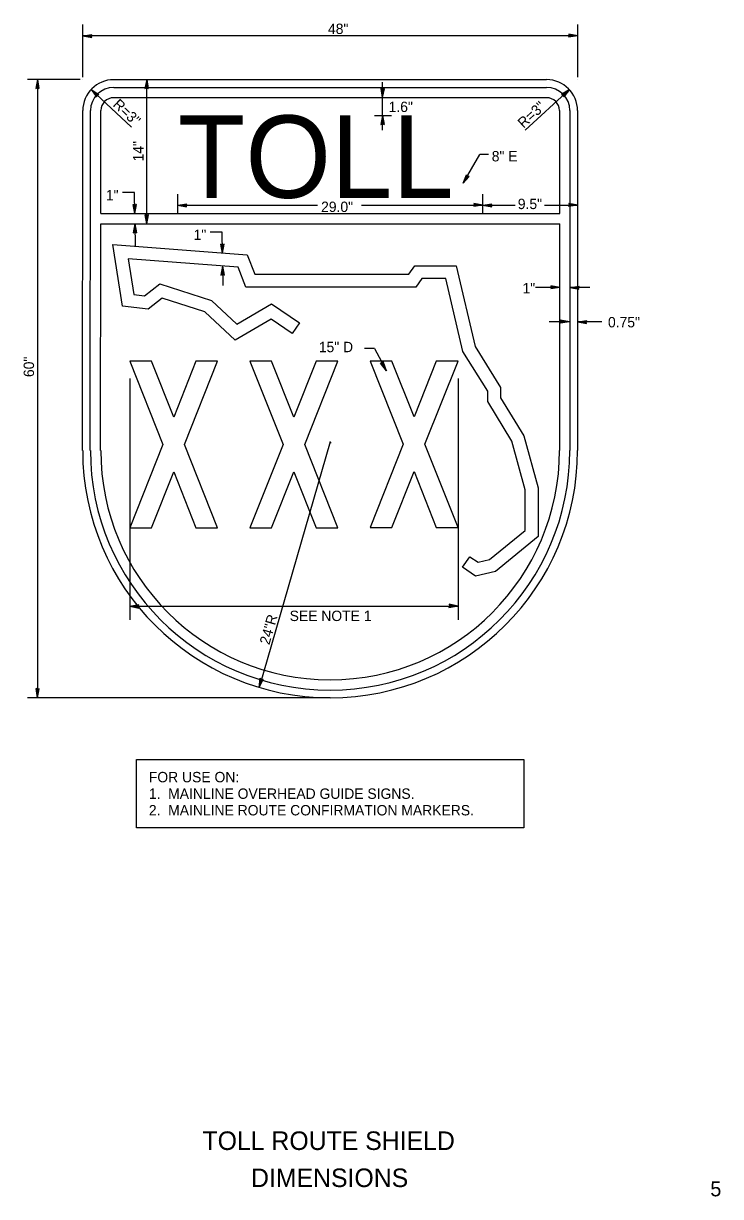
# Model space of a CAD drawing. Extents: x 52194 to 54069, y 8993 to 10153.
# Drawn here: x 53506 to 54069, y 9023 to 9972 of the extents above; entities that cross this region are included whole.
import ezdxf

# ---------------------------------------------------------------- set-up
doc = ezdxf.new("R2010")
doc.units = 0
for name, color, linetype in [('GSDims', 7, 'Continuous'), ('SignPanel', 7, 'Continuous'), ('TextLabel', 7, 'Continuous'), ('TextMisc', 7, 'Continuous'), ('TextShtNo', 7, 'Continuous')]:
    doc.layers.add(name, color=color, linetype=linetype)

msp = doc.modelspace()

# ---------------------------------------------------------------- linework, layer by layer
at = {"layer": 'GSDims'}
for p, q in [((53553.67, 9929.08), (53553.67, 9971.68)), ((53953.67, 9929.08), (53953.67, 9971.68)), ((53553.67, 9962.43), (53560.97, 9963.58)), ((53553.67, 9962.43), (53560.67, 9962.93)), ((53553.67, 9962.43), (53560.92, 9961.03)), ((53553.67, 9962.43), (53560.67, 9961.68)), ((53953.67, 9962.43), (53553.67, 9962.43)), ((53560.42, 9962.33), (53560.97, 9963.58)), ((53560.92, 9961.03), (53560.42, 9962.33)), ((53946.92, 9962.53), (53946.37, 9961.28)), ((53953.67, 9962.43), (53946.37, 9961.28)), ((53953.67, 9962.43), (53946.42, 9963.83)), ((53946.42, 9963.83), (53946.92, 9962.53)), ((53953.67, 9962.43), (53946.67, 9963.18)), ((53953.67, 9962.43), (53946.67, 9961.93)), ((53551.62, 9927.03), (53509.02, 9927.03)), ((53517.12, 9927.03), (53515.72, 9919.78)), ((53517.12, 9927.03), (53516.37, 9920.03)), ((53517.12, 9927.03), (53518.27, 9919.73)), ((53517.12, 9927.03), (53517.62, 9920.03)), ((53517.12, 9927.03), (53517.12, 9427.03)), ((53553.67, 9927.03), (53553.67, 9927.03)), ((53605.32, 9927.03), (53603.92, 9919.78)), ((53605.32, 9927.03), (53604.57, 9920.03)), ((53605.32, 9927.03), (53606.47, 9919.73)), ((53605.32, 9927.03), (53605.82, 9920.03)), ((53605.32, 9810.33), (53605.32, 9927.03)), ((53953.67, 9927.03), (53953.67, 9927.03)), ((53515.72, 9919.78), (53517.02, 9920.28)), ((53517.02, 9920.28), (53518.27, 9919.73)), ((53560.47, 9919.13), (53566.57, 9914.98)), ((53560.47, 9919.13), (53564.77, 9913.13)), ((53560.47, 9919.13), (53565.07, 9913.83)), ((53560.47, 9919.13), (53565.92, 9914.68)), ((53560.47, 9919.13), (53592.92, 9888.53)), ((53603.92, 9919.78), (53605.22, 9920.28)), ((53605.22, 9920.28), (53606.47, 9919.73)), ((53796.02, 9912.43), (53794.87, 9919.73)), ((53796.12, 9919.18), (53794.87, 9919.73)), ((53796.02, 9912.43), (53795.52, 9919.43)), ((53796.02, 9912.43), (53796.02, 9925.03)), ((53796.02, 9912.43), (53797.42, 9919.68)), ((53796.02, 9912.43), (53796.77, 9919.43)), ((53797.42, 9919.68), (53796.12, 9919.18)), ((53946.97, 9918.93), (53911.22, 9886.03)), ((53946.97, 9918.93), (53940.67, 9915.03)), ((53946.97, 9918.93), (53941.32, 9914.73)), ((53946.97, 9918.93), (53942.17, 9913.83)), ((53946.97, 9918.93), (53942.37, 9913.13)), ((53564.77, 9913.13), (53565.27, 9914.43)), ((53565.27, 9914.43), (53566.57, 9914.98)), ((53796.02, 9898.03), (53796.02, 9912.43)), ((53940.67, 9915.03), (53941.92, 9914.43)), ((53941.92, 9914.43), (53942.37, 9913.13)), ((53789.42, 9898.03), (53803.07, 9898.03)), ((53796.02, 9898.03), (53794.62, 9890.78)), ((53796.02, 9898.03), (53795.27, 9891.03)), ((53796.02, 9886.03), (53796.02, 9898.03)), ((53796.02, 9898.03), (53797.17, 9890.73)), ((53796.02, 9898.03), (53796.52, 9891.03)), ((53794.62, 9890.78), (53795.92, 9891.28)), ((53795.92, 9891.28), (53797.17, 9890.73)), ((53861.07, 9843.13), (53874.47, 9866.33)), ((53881.67, 9866.33), (53874.47, 9866.33)), ((53861.07, 9843.13), (53863.72, 9850.03)), ((53861.07, 9843.13), (53864.17, 9849.43)), ((53861.07, 9843.13), (53865.22, 9848.83)), ((53861.07, 9843.13), (53865.92, 9848.73)), ((53864.52, 9848.88), (53863.72, 9850.03)), ((53865.92, 9848.73), (53864.52, 9848.88)), ((53595.47, 9835.68), (53585.72, 9835.68)), ((53595.62, 9818.73), (53595.47, 9835.68)), ((53630.37, 9818.63), (53630.37, 9834.23)), ((53877.07, 9818.63), (53877.07, 9834.23)), ((53595.62, 9818.73), (53594.37, 9826.03)), ((53595.67, 9825.48), (53594.37, 9826.03)), ((53595.62, 9818.73), (53595.07, 9825.73)), ((53595.62, 9818.73), (53596.97, 9826.03)), ((53595.62, 9818.73), (53596.27, 9825.73)), ((53596.97, 9826.03), (53595.67, 9825.48)), ((53630.37, 9825.43), (53637.67, 9826.58)), ((53630.37, 9825.43), (53637.37, 9825.93)), ((53630.37, 9825.43), (53637.62, 9824.03)), ((53630.37, 9825.43), (53637.37, 9824.68)), ((53630.37, 9825.43), (53743.27, 9825.43)), ((53637.12, 9825.33), (53637.67, 9826.58)), ((53637.62, 9824.03), (53637.12, 9825.33)), ((53778.85, 9825.43), (53877.07, 9825.43)), ((53870.32, 9825.53), (53869.77, 9824.28)), ((53877.07, 9825.43), (53869.77, 9824.28)), ((53877.07, 9825.43), (53869.82, 9826.83)), ((53869.82, 9826.83), (53870.32, 9825.53)), ((53877.07, 9825.43), (53870.07, 9826.18)), ((53877.07, 9825.43), (53870.07, 9824.93)), ((53877.07, 9825.43), (53884.37, 9826.58)), ((53877.07, 9825.43), (53884.07, 9825.93)), ((53877.07, 9825.43), (53884.32, 9824.03)), ((53877.07, 9825.43), (53884.07, 9824.68)), ((53877.07, 9825.43), (53903.13, 9825.43)), ((53883.82, 9825.33), (53884.37, 9826.58)), ((53884.32, 9824.03), (53883.82, 9825.33)), ((53926.79, 9825.43), (53953.67, 9825.43)), ((53946.92, 9825.53), (53946.37, 9824.28)), ((53953.67, 9825.43), (53946.37, 9824.28)), ((53953.67, 9825.43), (53946.42, 9826.83)), ((53946.42, 9826.83), (53946.92, 9825.53)), ((53953.67, 9825.43), (53946.67, 9826.18)), ((53953.67, 9825.43), (53946.67, 9824.93)), ((53605.32, 9810.33), (53604.17, 9817.63)), ((53605.42, 9817.08), (53604.17, 9817.63)), ((53605.32, 9810.33), (53604.82, 9817.33)), ((53605.32, 9810.33), (53606.72, 9817.58)), ((53605.32, 9810.33), (53606.07, 9817.33)), ((53606.72, 9817.58), (53605.42, 9817.08)), ((53595.72, 9810.43), (53594.37, 9803.13)), ((53594.37, 9803.13), (53595.67, 9803.68)), ((53595.72, 9810.43), (53595.07, 9803.43)), ((53595.67, 9803.68), (53596.97, 9803.13)), ((53595.72, 9810.43), (53596.97, 9803.13)), ((53595.72, 9810.43), (53596.27, 9803.43)), ((53595.72, 9810.43), (53595.92, 9792.38)), ((53666.4, 9803.68), (53656.65, 9803.68)), ((53666.55, 9786.73), (53666.4, 9803.68)), ((53666.55, 9786.73), (53665.3, 9794.03)), ((53666.6, 9793.48), (53665.3, 9794.03)), ((53666.55, 9786.73), (53666, 9793.73)), ((53666.55, 9786.73), (53667.9, 9794.03)), ((53666.55, 9786.73), (53667.2, 9793.73)), ((53667.9, 9794.03), (53666.6, 9793.48)), ((53666.68, 9776.22), (53665.33, 9768.92)), ((53666.68, 9776.22), (53666.03, 9769.22)), ((53666.68, 9776.22), (53667.93, 9768.92)), ((53666.68, 9776.22), (53667.23, 9769.22)), ((53666.68, 9776.22), (53666.85, 9760.38)), ((53665.33, 9768.92), (53666.63, 9769.47)), ((53666.63, 9769.47), (53667.93, 9768.92)), ((53939.17, 9758.88), (53919.62, 9758.88)), ((53932.42, 9758.98), (53931.87, 9757.73)), ((53939.17, 9758.88), (53931.87, 9757.73)), ((53939.17, 9758.88), (53931.92, 9760.28)), ((53931.92, 9760.28), (53932.42, 9758.98)), ((53939.17, 9758.88), (53932.17, 9759.63)), ((53939.17, 9758.88), (53932.17, 9758.38)), ((53947.47, 9758.88), (53954.77, 9760.03)), ((53947.47, 9758.88), (53954.47, 9759.38)), ((53947.47, 9758.88), (53954.72, 9757.48)), ((53947.47, 9758.88), (53954.47, 9758.13)), ((53963.47, 9758.88), (53947.47, 9758.88)), ((53954.22, 9758.78), (53954.77, 9760.03)), ((53954.72, 9757.48), (53954.22, 9758.78)), ((53947.02, 9731.08), (53930.52, 9731.08)), ((53940.27, 9731.18), (53939.72, 9729.93)), ((53947.02, 9731.08), (53939.72, 9729.93)), ((53947.02, 9731.08), (53939.77, 9732.48)), ((53939.77, 9732.48), (53940.27, 9731.18)), ((53947.02, 9731.08), (53940.02, 9731.83)), ((53947.02, 9731.08), (53940.02, 9730.58)), ((53953.67, 9731.08), (53960.97, 9732.23)), ((53953.67, 9731.08), (53960.67, 9731.58)), ((53953.67, 9731.08), (53960.92, 9729.68)), ((53953.67, 9731.08), (53960.67, 9730.33)), ((53973.22, 9731.08), (53953.67, 9731.08)), ((53960.42, 9730.98), (53960.97, 9732.23)), ((53960.92, 9729.68), (53960.42, 9730.98)), ((53789.47, 9709.42), (53781.4, 9709.42)), ((53789.47, 9709.42), (53799.02, 9691.33)), ((53796.58, 9699), (53795.75, 9697.75)), ((53799.02, 9691.33), (53796.58, 9699)), ((53795.75, 9697.75), (53794.35, 9697.62)), ((53799.02, 9691.33), (53794.35, 9697.62)), ((53799.02, 9691.33), (53795.1, 9697.72)), ((53799.02, 9691.33), (53796.15, 9698.39)), ((53591.6, 9685.11), (53591.6, 9490.01)), ((53856.95, 9685.11), (53856.95, 9490.01)), ((53753.62, 9633.93), (53696.32, 9435.36)), ((53753.62, 9633.93), (53753.62, 9633.93)), ((53753.62, 9633.93), (53753.62, 9633.93)), ((53591.6, 9501.08), (53598.91, 9502.34)), ((53591.6, 9501.08), (53598.61, 9501.63)), ((53591.6, 9501.08), (53856.95, 9501.08)), ((53591.6, 9501.08), (53598.86, 9499.55)), ((53591.6, 9501.08), (53598.61, 9500.26)), ((53598.36, 9500.97), (53598.91, 9502.34)), ((53598.86, 9499.55), (53598.36, 9500.97)), ((53850.19, 9501.19), (53849.63, 9499.82)), ((53856.95, 9501.08), (53849.63, 9499.82)), ((53856.95, 9501.08), (53849.68, 9502.61)), ((53849.68, 9502.61), (53850.19, 9501.19)), ((53856.95, 9501.08), (53849.93, 9501.9)), ((53856.95, 9501.08), (53849.93, 9500.53)), ((53696.32, 9435.36), (53696.97, 9442.71)), ((53696.97, 9442.71), (53698.12, 9441.86)), ((53517.12, 9427.03), (53515.97, 9434.33)), ((53517.22, 9433.78), (53515.97, 9434.33)), ((53517.12, 9427.03), (53516.62, 9434.03)), ((53517.12, 9427.03), (53518.52, 9434.28)), ((53517.12, 9427.03), (53517.87, 9434.03)), ((53518.52, 9434.28), (53517.22, 9433.78)), ((53696.32, 9435.36), (53697.57, 9442.31)), ((53696.32, 9435.36), (53699.47, 9442.06)), ((53696.32, 9435.36), (53698.77, 9441.96)), ((53698.12, 9441.86), (53699.47, 9442.06)), ((53753.57, 9427.03), (53509.02, 9427.03)), ((53553.67, 9426.93), (53553.67, 9426.93))]:
    msp.add_line(p, q, dxfattribs=at)
for radius in [0.141, 0.141, 0.0707]:
    msp.add_circle((53753.62, 9633.93), radius, dxfattribs=at)
at = {"layer": 'SignPanel'}
for p, q in [((53578.67, 9927.03), (53928.57, 9927.03)), ((53578.67, 9920.73), (53928.57, 9920.73)), ((53578.67, 9912.43), (53928.57, 9912.43)), ((53553.57, 9626.93), (53553.67, 9902.03)), ((53559.77, 9626.93), (53559.87, 9902.03)), ((53568.17, 9818.63), (53568.17, 9902.03)), ((53939.17, 9818.63), (53939.17, 9902.03)), ((53947.47, 9626.93), (53947.47, 9902.03)), ((53953.67, 9626.93), (53953.67, 9902.03)), ((53568.17, 9818.63), (53620.37, 9818.63)), ((53620.37, 9818.63), (53939.17, 9818.63)), ((53568.07, 9626.93), (53568.17, 9810.33)), ((53568.17, 9810.33), (53939.17, 9810.33)), ((53939.17, 9626.93), (53939.17, 9810.33)), ((53577.98, 9793.57), (53686.64, 9785.19)), ((53585.72, 9743.87), (53577.98, 9793.57)), ((53686.64, 9785.19), (53692.71, 9769.56)), ((53679.26, 9775.24), (53590.37, 9782.1)), ((53590.37, 9782.1), (53594.86, 9753.3)), ((53685.54, 9759.08), (53679.26, 9775.24)), ((53817.33, 9769.56), (53822.03, 9776.5)), ((53822.03, 9776.5), (53855.56, 9776.5)), ((53855.56, 9776.5), (53870.74, 9711.18)), ((53692.71, 9769.56), (53817.33, 9769.56)), ((53827.59, 9766.03), (53822.9, 9759.08)), ((53847.24, 9766.03), (53827.59, 9766.03)), ((53860.93, 9707.12), (53847.24, 9766.03)), ((53603.47, 9752.23), (53615.82, 9761.95)), ((53615.82, 9761.95), (53657.73, 9748.31)), ((53822.9, 9759.08), (53685.54, 9759.08)), ((53594.86, 9753.3), (53603.47, 9752.23)), ((53617.9, 9750.25), (53606.52, 9741.3)), ((53652.3, 9739.06), (53617.9, 9750.25)), ((53657.73, 9748.31), (53678.3, 9729.25)), ((53606.52, 9741.3), (53585.72, 9743.87)), ((53676.9, 9716.27), (53652.3, 9739.06)), ((53678.3, 9729.25), (53706.2, 9745.64)), ((53706.2, 9745.64), (53728.9, 9730.29)), ((53705.81, 9733.26), (53676.9, 9716.27)), ((53723.03, 9721.61), (53705.81, 9733.26)), ((53728.9, 9730.29), (53723.03, 9721.61)), ((53870.74, 9711.18), (53891.4, 9677.98)), ((53609.15, 9699.15), (53591.6, 9699.15)), ((53591.6, 9699.15), (53618.37, 9631.8)), ((53627.14, 9653.88), (53609.15, 9699.15)), ((53645.13, 9699.15), (53627.14, 9653.88)), ((53635.92, 9631.8), (53662.69, 9699.15)), ((53662.69, 9699.15), (53645.13, 9699.15)), ((53706.28, 9699.27), (53688.73, 9699.27)), ((53688.73, 9699.27), (53715.5, 9631.92)), ((53724.27, 9654), (53706.28, 9699.27)), ((53742.27, 9699.27), (53724.27, 9654)), ((53733.05, 9631.92), (53759.82, 9699.27)), ((53759.82, 9699.27), (53742.27, 9699.27)), ((53803.42, 9699.39), (53785.86, 9699.39)), ((53785.86, 9699.39), (53812.63, 9632.03)), ((53821.41, 9654.12), (53803.42, 9699.39)), ((53839.4, 9699.39), (53821.41, 9654.12)), ((53830.18, 9632.03), (53856.95, 9699.39)), ((53856.95, 9699.39), (53839.4, 9699.39)), ((53880.92, 9674.99), (53860.93, 9707.12)), ((53880.92, 9666.67), (53880.92, 9674.99)), ((53891.4, 9677.98), (53891.4, 9669.6)), ((53900.38, 9634.63), (53880.92, 9666.67)), ((53891.4, 9669.6), (53910.1, 9638.81)), ((53911.13, 9595.3), (53900.38, 9634.63)), ((53910.1, 9638.81), (53921.61, 9596.7)), ((53618.37, 9631.8), (53591.6, 9564.45)), ((53662.69, 9564.45), (53635.92, 9631.8)), ((53715.5, 9631.92), (53688.73, 9564.56)), ((53759.82, 9564.56), (53733.05, 9631.92)), ((53812.63, 9632.03), (53785.86, 9564.68)), ((53856.95, 9564.68), (53830.18, 9632.03)), ((53609.15, 9564.45), (53627.14, 9609.72)), ((53627.14, 9609.72), (53645.13, 9564.45)), ((53706.28, 9564.56), (53724.28, 9609.83)), ((53724.28, 9609.83), (53742.27, 9564.56)), ((53803.42, 9564.68), (53821.41, 9609.95)), ((53821.41, 9609.95), (53839.4, 9564.68)), ((53911.13, 9562.31), (53911.13, 9595.3)), ((53921.61, 9596.7), (53921.61, 9557.35)), ((53591.6, 9564.45), (53609.15, 9564.45)), ((53645.13, 9564.45), (53662.69, 9564.45)), ((53688.73, 9564.56), (53706.28, 9564.56)), ((53742.27, 9564.56), (53759.82, 9564.56)), ((53785.86, 9564.68), (53803.42, 9564.68)), ((53839.4, 9564.68), (53856.95, 9564.68)), ((53882.51, 9538.86), (53911.13, 9562.31)), ((53921.61, 9557.35), (53887.29, 9529.23)), ((53860.66, 9532.49), (53866.63, 9541.1)), ((53866.63, 9541.1), (53873.11, 9536.61)), ((53873.11, 9536.61), (53882.51, 9538.86)), ((53870.99, 9525.32), (53860.66, 9532.49)), ((53887.29, 9529.23), (53870.99, 9525.32))]:
    msp.add_line(p, q, dxfattribs=at)
for centre, radius, start, end in [((53578.67, 9901.98), 25, 90, 179.97916), ((53928.58, 9901.99), 25, 0, 90), ((53578.67, 9901.98), 18.75, 90, 179.97916), ((53928.58, 9901.99), 18.75, 0, 90), ((53578.67, 9901.98), 10.42, 90, 179.97916), ((53928.58, 9901.99), 10.42, 0, 90), ((53753.58, 9626.99), 200, 180, 0), ((53753.58, 9626.99), 193.75, 180, 0), ((53753.58, 9626.99), 185.42, 180, 0)]:
    msp.add_arc(centre, radius, start, end, dxfattribs=at)
at = {"layer": 'TextLabel'}
msp.add_lwpolyline([(53597.08, 9376.99), (53910.08, 9376.99), (53910.08, 9321.79), (53597.08, 9321.79)], close=True, dxfattribs=at)

# ---------------------------------------------------------------- texts
at = {"layer": 'GSDims'}
for s, p in [('48"', (53751.87, 9963.93)), ('1.6"', (53800.87, 9900.81)), ('8" E ', (53884.22, 9860.88)), ('1"', (53572.32, 9829.33)), ('29.0"', (53746.28, 9819.93)), ('9.5"', (53905.28, 9822.28)), ('1"', (53643.25, 9797.33)), ('1"', (53909.07, 9754.1)), ('0.75"', (53978.16, 9726.6)), ('15" D', (53744.45, 9706.52)), ('SEE NOTE 1', (53720.87, 9489.03))]:
    msp.add_text(s, height=8.4, dxfattribs=at).set_placement(p)
for s, rotation, p in [('R=3"', 316.65072, (53577.42, 9906.13)), ('R=3"', 42.60374, (53909.92, 9887.23)), ('14"', 90, (53602.77, 9860.83)), ('60"', 90, (53514.27, 9686.43)), ('.', 90, (53754.64, 9631.76)), ('24"R', 73.92331, (53704.42, 9469.31))]:
    msp.add_text(s, height=8.4, rotation=rotation, dxfattribs=at).set_placement(p)
at = {"layer": 'SignPanel'}
msp.add_text('TOLL', height=66.65, dxfattribs=at).set_placement((53630.62, 9831.38))
at = {"layer": 'TextLabel'}
for s, p in [('FOR USE ON:', (53607.08, 9358.59)), ('1.  MAINLINE OVERHEAD GUIDE SIGNS.', (53607.08, 9345.19)), ('2.  MAINLINE ROUTE CONFIRMATION MARKERS.', (53607.08, 9331.79))]:
    msp.add_text(s, height=8.4, dxfattribs=at).set_placement(p)
at = {"layer": 'TextMisc'}
for s, p in [('   TOLL ROUTE SHIELD    ', (53633.7, 9061.15)), ('       DIMENSIONS       ', (53650.64, 9031.15))]:
    msp.add_text(s, height=15, rotation=360, dxfattribs=at).set_placement(p)
at = {"layer": 'TextShtNo'}
msp.add_text('5', height=12, rotation=360, dxfattribs=at).set_placement((54060.87, 9023.65))

doc.saveas('drawing.dxf')
